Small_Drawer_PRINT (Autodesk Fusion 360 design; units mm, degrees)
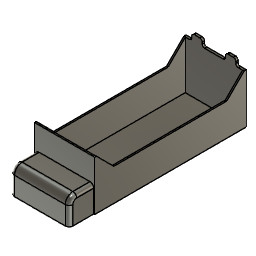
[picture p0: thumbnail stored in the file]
sketch "Sketch1" plane through (0, 0, 0) normal (0, 0, 1) x axis (1, 0, 0)
  line L1 (31.8, 0) -> (0, 0)
  line L2 (31.8, 80) -> (31.8, 0)
  line L3 (0, 80) -> (31.8, 80)
  line L4 (0, 0) -> (0, 80)
  point P1 (0, 0)
  point P2 (0, 0)
  point P3 (31.8, 0)
  point P4 (31.8, 80)
  horizontal L1
  vertical L2
  horizontal L3
  vertical L4
  coincident P1 P2
  dimension "d1" distance P2 P3 = 31.8
  dimension "d2" distance P3 P4 = 80
extrude "Extrude1" new body sketch "Sketch1" along normal blind 26.2
shell "Shell1" innerThickness 0.8
work_plane "WorkPlane1" AlongDistance -18.4
sketch "Sketch3" plane through (0, 80, 0) normal (0, 1, 0) x axis (-1, 0, 0)
  line L1 (0, 0) -> (-31.8, 0)
  line L2 (0, 26.2) -> (0, 0)
  line L3 (-31.8, 26.2) -> (0, 26.2)
  line L4 (-31.8, 0) -> (-31.8, 26.2)
  line L5 (-15.9, 0) -> (-15.9, 26.2)
  line L6 (-27.55, 28.45) -> (-27.55, 27.45)
  line L7 (-23.3, 29.7) -> (-26.3, 29.7)
  line L8 (-22.05, 27.45) -> (-22.05, 28.45)
  line L9 (-20.8, 26.2) -> (-28.8, 26.2)
  line L10 (-8.5, 29.7) -> (-5.5, 29.7)
  line L11 (-4.25, 28.45) -> (-4.25, 27.45)
  line L12 (-11, 26.2) -> (-3, 26.2)
  line L13 (-9.75, 27.45) -> (-9.75, 28.45)
  arc A1 centre (-28.8, 27.45) radius 1.25 clockwise from (-27.55, 27.45) to (-28.8, 26.2)
  arc A2 centre (-26.3, 28.45) radius 1.25 clockwise from (-27.55, 28.45) to (-26.3, 29.7)
  arc A3 centre (-23.3, 28.45) radius 1.25 clockwise from (-23.3, 29.7) to (-22.05, 28.45)
  arc A4 centre (-20.8, 27.45) radius 1.25 clockwise from (-20.8, 26.2) to (-22.05, 27.45)
  arc A5 centre (-5.5, 28.45) radius 1.25 clockwise from (-5.5, 29.7) to (-4.25, 28.45)
  arc A6 centre (-11, 27.45) radius 1.25 clockwise from (-9.75, 27.45) to (-11, 26.2)
  arc A7 centre (-3, 27.45) radius 1.25 clockwise from (-3, 26.2) to (-4.25, 27.45)
  arc A8 centre (-8.5, 28.45) radius 1.25 clockwise from (-9.75, 28.45) to (-8.5, 29.7)
  point P10 (-15.9, 26.2)
  point P11 (-15.9, 0)
  point P20 (-24.8, 29.7)
  point P12 (-27.55, 27.45)
  point P27 (-4.25, 27.45)
  point P13 (-27.55, 28.45)
  point P21 (-4.25, 28.45)
  point P14 (-26.3, 29.7)
  point P28 (-5.5, 29.7)
  point P15 (-23.3, 29.7)
  point P26 (-8.5, 29.7)
  point P16 (-22.05, 28.45)
  point P23 (-9.75, 28.45)
  point P17 (-22.05, 27.45)
  point P22 (-9.75, 27.45)
  point P18 (-28.8, 26.2)
  point P30 (-3, 26.2)
  point P19 (-20.8, 26.2)
  point P29 (-11, 26.2)
  point P31 (-7, 29.7)
  midpoint L3 P10
  perpendicular L3 L5
  coincident L1 P11
  horizontal L7
  tangent L7 A2
  tangent L6 A2
  tangent L6 A1
  tangent L7 A3
  tangent L8 A3
  tangent L8 A4
  tangent L9 A4
  tangent L9 A1
  equal A1 A2
  equal A2 A3
  equal A3 A4
  collinear L3 L9
  vertical L8
  vertical L6
  midpoint L7 P20
  symmetric L5 P12 P27
  symmetric L5 P13 P21
  symmetric L5 P14 P28
  symmetric L5 P15 P26
  symmetric L5 P16 P23
  symmetric L5 P17 P22
  symmetric L5 P18 P30
  symmetric L5 P19 P29
  symmetric L5 P20 P31
  symmetric L5 A1 A7
  symmetric L5 A2 A5
  symmetric L5 A3 A8
  symmetric L5 A4 A6
  dimension "d18" distance L4 P20 = 7
  dimension "d19" distance L7 L9 = 3.5
  dimension "d20" distance L6 L8 = 5.5
  dimension "d21" radius A1 = 1.25
extrude "Extrude3" add sketch "Sketch3" profile of L3 A1 A2 A3 A4 L6 L7 L8 L9 A5 L10 A6 A7 L11 L12 A8 L13 against normal blind 0.8
sketch "Sketch4" plane through (31.8, 0, 0) normal (1, 0, 0) x axis (0, 1, 0)
  line L1 (80, 0) -> (0, 0)
  line L2 (80, 26.2) -> (80, 0)
  line L3 (0, 26.2) -> (80, 26.2)
  line L4 (0, 0) -> (0, 26.2)
  line L5 (10.1071, 17) -> (0.9071, 26.2)
  line L6 (7.8528, 26.2) -> (0.9071, 26.2)
  line L7 (69.7311, 17) -> (10.1071, 17)
  line L8 (78.9311, 26.2) -> (69.7311, 17)
  line L9 (0.9071, 26.2) -> (78.9311, 26.2)
  point P6 (0.9071, 26.2)
  point P10 (78.9311, 26.2)
  horizontal L6
  coincident L3 P6
  horizontal L7
  coincident L3 P10
  dimension "d24" angle L5 L6 = 45
  dimension "d25" angle L7 L8 = 135
  dimension "d26" distance L1 L7 = 17
extrude "Extrude4" cut sketch "Sketch4" profile of L3 L5 L7 L8 L9 against normal blind 31.8
extrude "Extrude5" add of existing geometry blind 0.4
sketch "Sketch5" plane through (0, 0, 0) normal (0, -1, 0) x axis (1, 0, 0)
  line L1 (31.8, 0) -> (0, 0)
  line L2 (31.8, 26.2) -> (31.8, 0)
  line L3 (0, 26.2) -> (31.8, 26.2)
  line L4 (0, 0) -> (0, 26.2)
  line L5 (31.3, 13.8) -> (0.5, 13.8)
  line L6 (31.3, 13) -> (31.3, 13.8)
  line L7 (0.5, 13) -> (31.3, 13)
  line L8 (0.5, 13.8) -> (0.5, 13)
  horizontal L5
  vertical L6
  horizontal L7
  vertical L8
  dimension "d31" distance L4 L8 = 0.5
  dimension "d32" distance L2 L6 = 0.5
  dimension "d33" distance L5 L7 = 0.8
  dimension "d34" distance L1 L7 = 13
extrude "Extrude6" add sketch "Sketch5" profile of L5 L6 L7 L8 along normal blind 13
sketch "Sketch6" plane through (0, 0, 13) normal (0, 0, -1) x axis (1, 0, 0)
  line L1 (31.3, 0) -> (0.5, 0)
  line L2 (31.3, 13) -> (31.3, 0)
  line L3 (0.5, 13) -> (31.3, 13)
  line L4 (0.5, 0) -> (0.5, 13)
  line L5 (31.3, 13) -> (0.5, 13)
  line L6 (31.3, 12.2) -> (31.3, 13)
  line L7 (0.5, 12.2) -> (31.3, 12.2)
  line L8 (0.5, 13) -> (0.5, 12.2)
  point P5 (0.5, 13)
  point P6 (0.5, 13)
  point P9 (0.5, 12.2)
  horizontal L5
  vertical L6
  horizontal L7
  vertical L8
  coincident P5 P6
  dimension "d37" distance P6 P9 = 0.8
extrude "Extrude7" add sketch "Sketch6" profile of L2 L3 L4 L5 L6 L7 L8 along normal blind 13
sketch "Sketch8" plane through (0, 0, 13) normal (0, 0, -1) x axis (1, 0, 0)
  line L1 (0.5, 12.2) -> (31.3, 12.2)
  line L2 (0.5, 0) -> (0.5, 12.2)
  line L3 (31.3, 0) -> (0.5, 0)
  line L4 (31.3, 12.2) -> (31.3, 0)
  line L5 (0.5, 0) -> (1.3, 0)
  line L6 (0.5, 12.2) -> (0.5, 0)
  line L7 (1.3, 12.2) -> (0.5, 12.2)
  line L8 (1.3, 0) -> (1.3, 12.2)
  line L9 (30.5, 0) -> (31.3, 0)
  line L10 (30.5, 12.2) -> (30.5, 0)
  line L11 (31.3, 12.2) -> (30.5, 12.2)
  line L12 (31.3, 0) -> (31.3, 12.2)
  point P3 (0.5, 12.2)
  point P8 (0.5, 12.2)
  point P6 (1.3, 0)
  point P12 (30.5, 12.2)
  point P5 (31.3, 0)
  point P10 (31.3, 0)
  point P13 (31.3, 12.2)
  point P9 (1.3, 12.2)
  horizontal L5
  vertical L6
  horizontal L7
  vertical L8
  coincident P3 P8
  coincident L3 P6
  horizontal L9
  vertical L10
  horizontal L11
  vertical L12
  coincident L1 P12
  coincident P5 P10
  dimension "d45" distance P12 P13 = 0.8
  dimension "d46" distance P8 P9 = 0.8
extrude "Extrude9" add sketch "Sketch8" along normal blind 13
fillet "Fillet2" radius 4
chamfer "Chamfer1" distance 3
fillet "Fillet3" radius 2
fillet "Fillet4" radius 2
